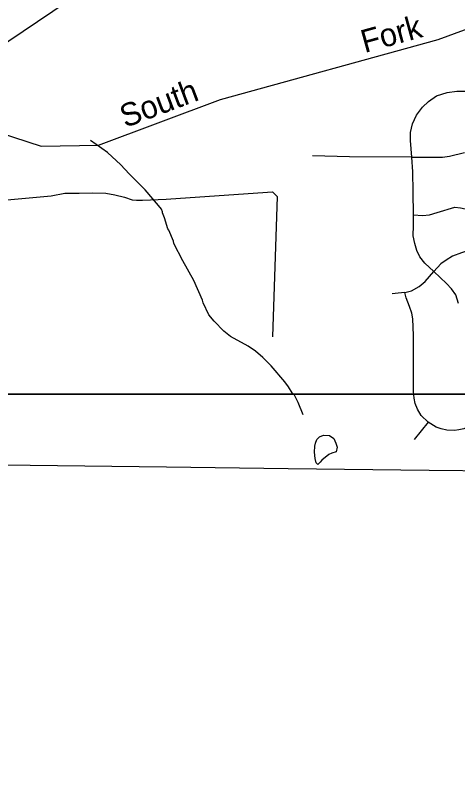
# Model space of a CAD drawing. Extents: x 1547597 to 1699558, y 810033 to 920809.
# Drawn here: x 1641727 to 1644617, y 828797 to 833780 of the extents above; entities that cross this region are included whole.
import ezdxf

# ---------------------------------------------------------------- set-up
doc = ezdxf.new("R2010")
doc.units = 0
for name, color, linetype in [('Exist Boundary Political CountyLine', 7, 'Continuous'), ('Exist Hydrographic Creek Single Shore', 7, 'Continuous'), ('Exist Hydrographic Creek Single Shore Label', 7, 'Continuous'), ('Exist Hydrographic Misc Water Feature', 7, 'Continuous'), ('Exist Road Non-System Type 51', 7, 'Continuous'), ('Exist Utilities Electrical Transmission Line', 7, 'Continuous'), ('Map Preparation Inset Cut Line', 7, 'Continuous')]:
    doc.layers.add(name, color=color, linetype=linetype)

msp = doc.modelspace()

# ---------------------------------------------------------------- linework, layer by layer
at = {"layer": 'Exist Boundary Political CountyLine'}
msp.add_lwpolyline([(1641106.9, 830851.7), (1641824.3, 830844.7), (1642715.3, 830833.2), (1643508.5, 830822.6), (1644430, 830810.8), (1645304.9, 830801.6)], dxfattribs=at)
at = {"layer": 'Exist Hydrographic Creek Single Shore'}
msp.add_lwpolyline([(1640695.4, 833463.4), (1640991.9, 833289.7), (1641439, 833073.9), (1641896, 832926.7), (1642271, 832932.2), (1643067.1, 833231.2), (1644489, 833622.5), (1645301, 833921.1), (1645727.1, 833991.3), (1646519.1, 834004.7), (1647004.1, 834149.1)], dxfattribs=at)
at = {"layer": 'Exist Hydrographic Misc Water Feature'}
for points in [[(1643606.9, 831171.4), (1643575.5, 831251.7), (1643549.9, 831299.9), (1643536, 831316), (1643512.3, 831356.1), (1643488.6, 831388.2), (1643399.4, 831492.9), (1643343.8, 831547.3), (1643296.1, 831587.6), (1643248.4, 831620), (1643133, 831682.9), (1643089.3, 831719.2), (1643025.9, 831783.7), (1642992.1, 831823.9), (1642954.7, 831904.2), (1642950.8, 831920.2), (1642893.8, 832048.6), (1642820.8, 832177.1), (1642763.6, 832289.4), (1642759.7, 832305.4), (1642730.3, 832377.6), (1642724.3, 832385.7), (1642702.9, 832457.8), (1642689.1, 832489.9), (1642689.2, 832497.9), (1642681.3, 832513.9), (1642663.4, 832538.1), (1642576.3, 832640.7), (1642471.1, 832745.4), (1642417.6, 832803.8), (1642330.2, 832884.4), (1642218.7, 832962.9)], [(1643702.8, 830847.1), (1643691.6, 830859.7), (1643685.1, 830886.8), (1643681.2, 830928.5), (1643683, 830968), (1643686.9, 830986.8), (1643697.1, 831011.4), (1643714.8, 831029.4), (1643740, 831040.6), (1643780.1, 831036.7), (1643807, 831017.1), (1643821.5, 830986.5), (1643830, 830961), (1643823.5, 830931.4), (1643794.7, 830922.3), (1643774.6, 830914.4), (1643728.9, 830877.5), (1643718.6, 830862.4), (1643702.8, 830847.1)]]:
    msp.add_lwpolyline(points, dxfattribs=at)
at = {"layer": 'Exist Road Non-System Type 51'}
msp.add_line((1644423.2, 831124.4), (1644332.6, 831010.7), dxfattribs=at)
for points in [[(1644316.3, 832854.8), (1644307.6, 832962.8), (1644307.6, 833014.8), (1644321.1, 833070.7), (1644348.1, 833128.5), (1644386.6, 833180.5), (1644425.1, 833217.1), (1644479.1, 833253.7), (1644548.5, 833274.9), (1644610.1, 833284.6), (1644662.2, 833284.6), (1644739.2, 833265.3), (1644785.5, 833244.1), (1644852, 833201.7), (1644931, 833122.7), (1644987.8, 833074.5)], [(1644316.3, 832854.8), (1644517.6, 832854.8), (1644563.9, 832860.6), (1644660.2, 832883.8)], [(1644316.3, 832854.8), (1643910.6, 832856.8), (1643667.8, 832862.6)], [(1644327.8, 832477.2), (1644325.9, 832627.5), (1644324, 832758.5), (1644316.3, 832854.8)], [(1640731.9, 832523.1), (1641025.9, 832532.9), (1641321.4, 832546), (1641449.5, 832552.6), (1641600.5, 832569), (1641961.7, 832601.9), (1642050.3, 832618.3), (1642145.5, 832618.3), (1642234.2, 832621.6), (1642319.6, 832618.3), (1642378.7, 832608.4), (1642441, 832592), (1642490.3, 832575.6), (1642519.8, 832572.3), (1642559.2, 832572.3), (1642713.6, 832578.9), (1642933.5, 832595.3), (1643406.4, 832628.2), (1643436.6, 832596.6), (1643406.4, 831682)], [(1644327.8, 832477.2), (1644387.6, 832473.3), (1644431.9, 832477.2), (1644482, 832492.6), (1644597.6, 832527.3), (1644634.2, 832523.4), (1644665, 832517.6), (1644686.2, 832509.9)], [(1644459.8, 832107.2), (1644401, 832161.1), (1644368.3, 832203.5), (1644349, 832244), (1644335.5, 832290.2), (1644325.9, 832340.3), (1644327.8, 832407.8), (1644327.8, 832477.2)], [(1645037, 832324.9), (1644946.4, 832321.1), (1644861.6, 832301.8), (1644641.9, 832230.5), (1644582.2, 832207.4), (1644541.7, 832182.3), (1644507, 832157.3), (1644459.8, 832107.2)], [(1644271, 831970.4), (1644315.3, 831981.9), (1644365.4, 832008.9), (1644403.9, 832041.7), (1644459.8, 832107.2)], [(1644620.7, 831899.1), (1644604.3, 831954.9), (1644575.4, 831995.4), (1644542.7, 832030.1), (1644459.8, 832107.2)], [(1644271, 831970.4), (1644228.6, 831966.5), (1644188.1, 831962.6)], [(1644423.2, 831124.4), (1644377.9, 831168.7), (1644354.8, 831209.2), (1644339.4, 831245.8), (1644331.7, 831280.5), (1644327.8, 831324.8), (1644327.8, 831459.7), (1644327.8, 831690.9), (1644323, 831798.9), (1644317.2, 831835.5), (1644301.8, 831879.8), (1644280.6, 831935.7), (1644271, 831970.4)], [(1644781.6, 831164.9), (1644729.6, 831122.5), (1644689.1, 831095.5), (1644656.4, 831082), (1644623.6, 831074.3), (1644594.7, 831070.4), (1644546.5, 831072.4), (1644508, 831080.1), (1644475.2, 831091.6), (1644423.2, 831124.4)]]:
    msp.add_lwpolyline(points, dxfattribs=at)
at = {"layer": 'Exist Utilities Electrical Transmission Line'}
msp.add_lwpolyline([(1638715.4, 831642.6), (1639001.1, 831798.9), (1639250.9, 831957.7), (1639654.2, 832238.7), (1640105.9, 832544.9), (1640632, 832902.2), (1641160.1, 833257.3), (1641684.4, 833612.6), (1642160.2, 833934.5), (1642516.9, 834180), (1642617.8, 834246.6), (1642837.9, 834741.8), (1643132, 835398.2), (1643386.9, 835958.9), (1643675.7, 836651.2), (1643916.7, 837224.2), (1644162.1, 837819), (1644374.7, 838344.3), (1644719.4, 839206)], dxfattribs=at)
at = {"layer": 'Map Preparation Inset Cut Line'}
for points in [[(1694128.9, 831307.2), (1633724, 831307.2), (1633724, 874749.3), (1694128.9, 874749.3)], [(1641328.6, 831307.2), (1694128.9, 831307.2), (1694128.9, 823877.6), (1641328.6, 823877.6)]]:
    msp.add_lwpolyline(points, close=True, dxfattribs=at)

# ---------------------------------------------------------------- texts
at = {"layer": 'Exist Hydrographic Creek Single Shore Label'}
for s, rotation, p in [('Fork', 15.4266, (1644008.7, 833532.8)), ('South', 20.6237, (1642445.5, 833043.9))]:
    msp.add_text(s, height=150, rotation=rotation, dxfattribs=at).set_placement(p)

doc.saveas('drawing.dxf')
